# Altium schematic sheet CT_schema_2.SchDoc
size 298 x 247 mm
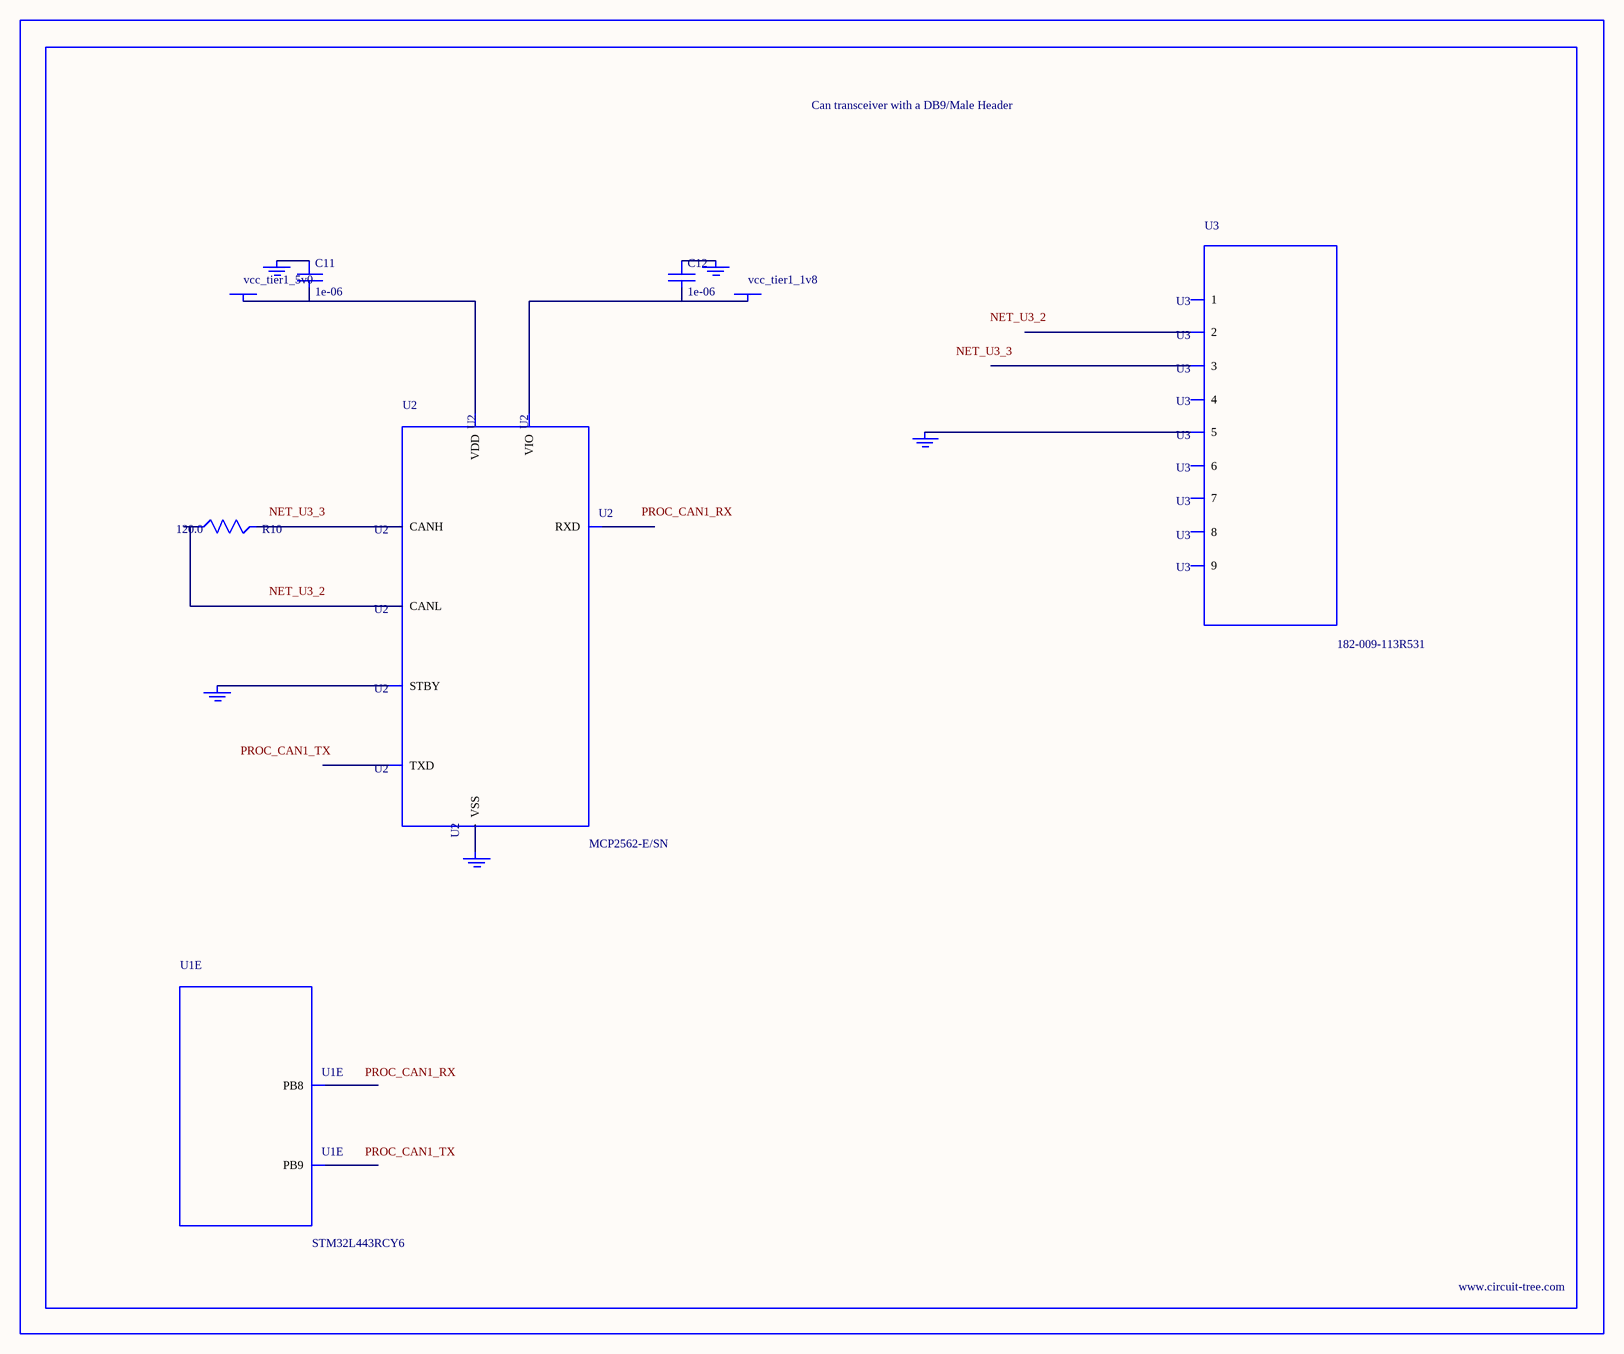
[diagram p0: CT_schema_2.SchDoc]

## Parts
BORDER1  (no value)
C11  1e-06  [C0603]
C12  1e-06  [C0603]
GND_INSTANCE_1_0  (no value)
GND_INSTANCE_1_1  (no value)
GND_INSTANCE_1_2  (no value)
GND_INSTANCE_1_3  (no value)
GND_INSTANCE_1_4  (no value)
POWER_INSTANCE_1_0  vcc_tier1_5v0
POWER_INSTANCE_1_1  vcc_tier1_1v8
R10  120.0  [R0603]
U1  STM32L443RCY6  [WLCSP64]  (part E of 7)
U2  MCP2562-E/SN  [SOIC-8]
U3  182-009-113R531  [182-009-MALE]

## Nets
NetC11_1: C11.1 GND_INSTANCE_1_0.0(GND)
NetC11_2: C11.2 POWER_INSTANCE_1_0.0(PWR) U2.3(VDD)
NetC12_1: C12.1 GND_INSTANCE_1_1.0(GND)
NetC12_2: C12.2 POWER_INSTANCE_1_1.0(PWR) U2.5(VIO)
NetGND_INSTANCE_1_2_0: GND_INSTANCE_1_2.0(GND) U2.8(STBY)
NetGND_INSTANCE_1_3_0: GND_INSTANCE_1_3.0(GND) U2.2(VSS)
NetGND_INSTANCE_1_4_0: GND_INSTANCE_1_4.0(GND) U3.5
NetR10_1: R10.1 U2.6(CANL)
NetR10_2: R10.2 U2.7(CANH)

Not connected (* = marked no-connect by the designer): U1 B6(PB9) C6(PB8); U2 1(TXD) 4(RXD); U3 1 2 3 4 6 7 8 9

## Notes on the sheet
- Labels drawn without touching a wire or pin: NET_U3_2, NET_U3_3, PROC_CAN1_RX, PROC_CAN1_TX

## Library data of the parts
BORDER1 = BORDER_PAGE1
C11 C12 = C0603C105K3RACTU
GND_INSTANCE_1_0-GND_INSTANCE_1_4 = GND
POWER_INSTANCE_1_0 POWER_INSTANCE_1_1 = PWR
R10 = RC0603JR-07120RL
